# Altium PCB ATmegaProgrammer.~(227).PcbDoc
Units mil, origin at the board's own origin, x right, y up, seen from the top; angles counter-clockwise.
Board outline 2130 x 2245 mil, 2 copper layers (Top Layer, Bottom Layer); 13 components, 10 nets, 72 pads, 3 vias.
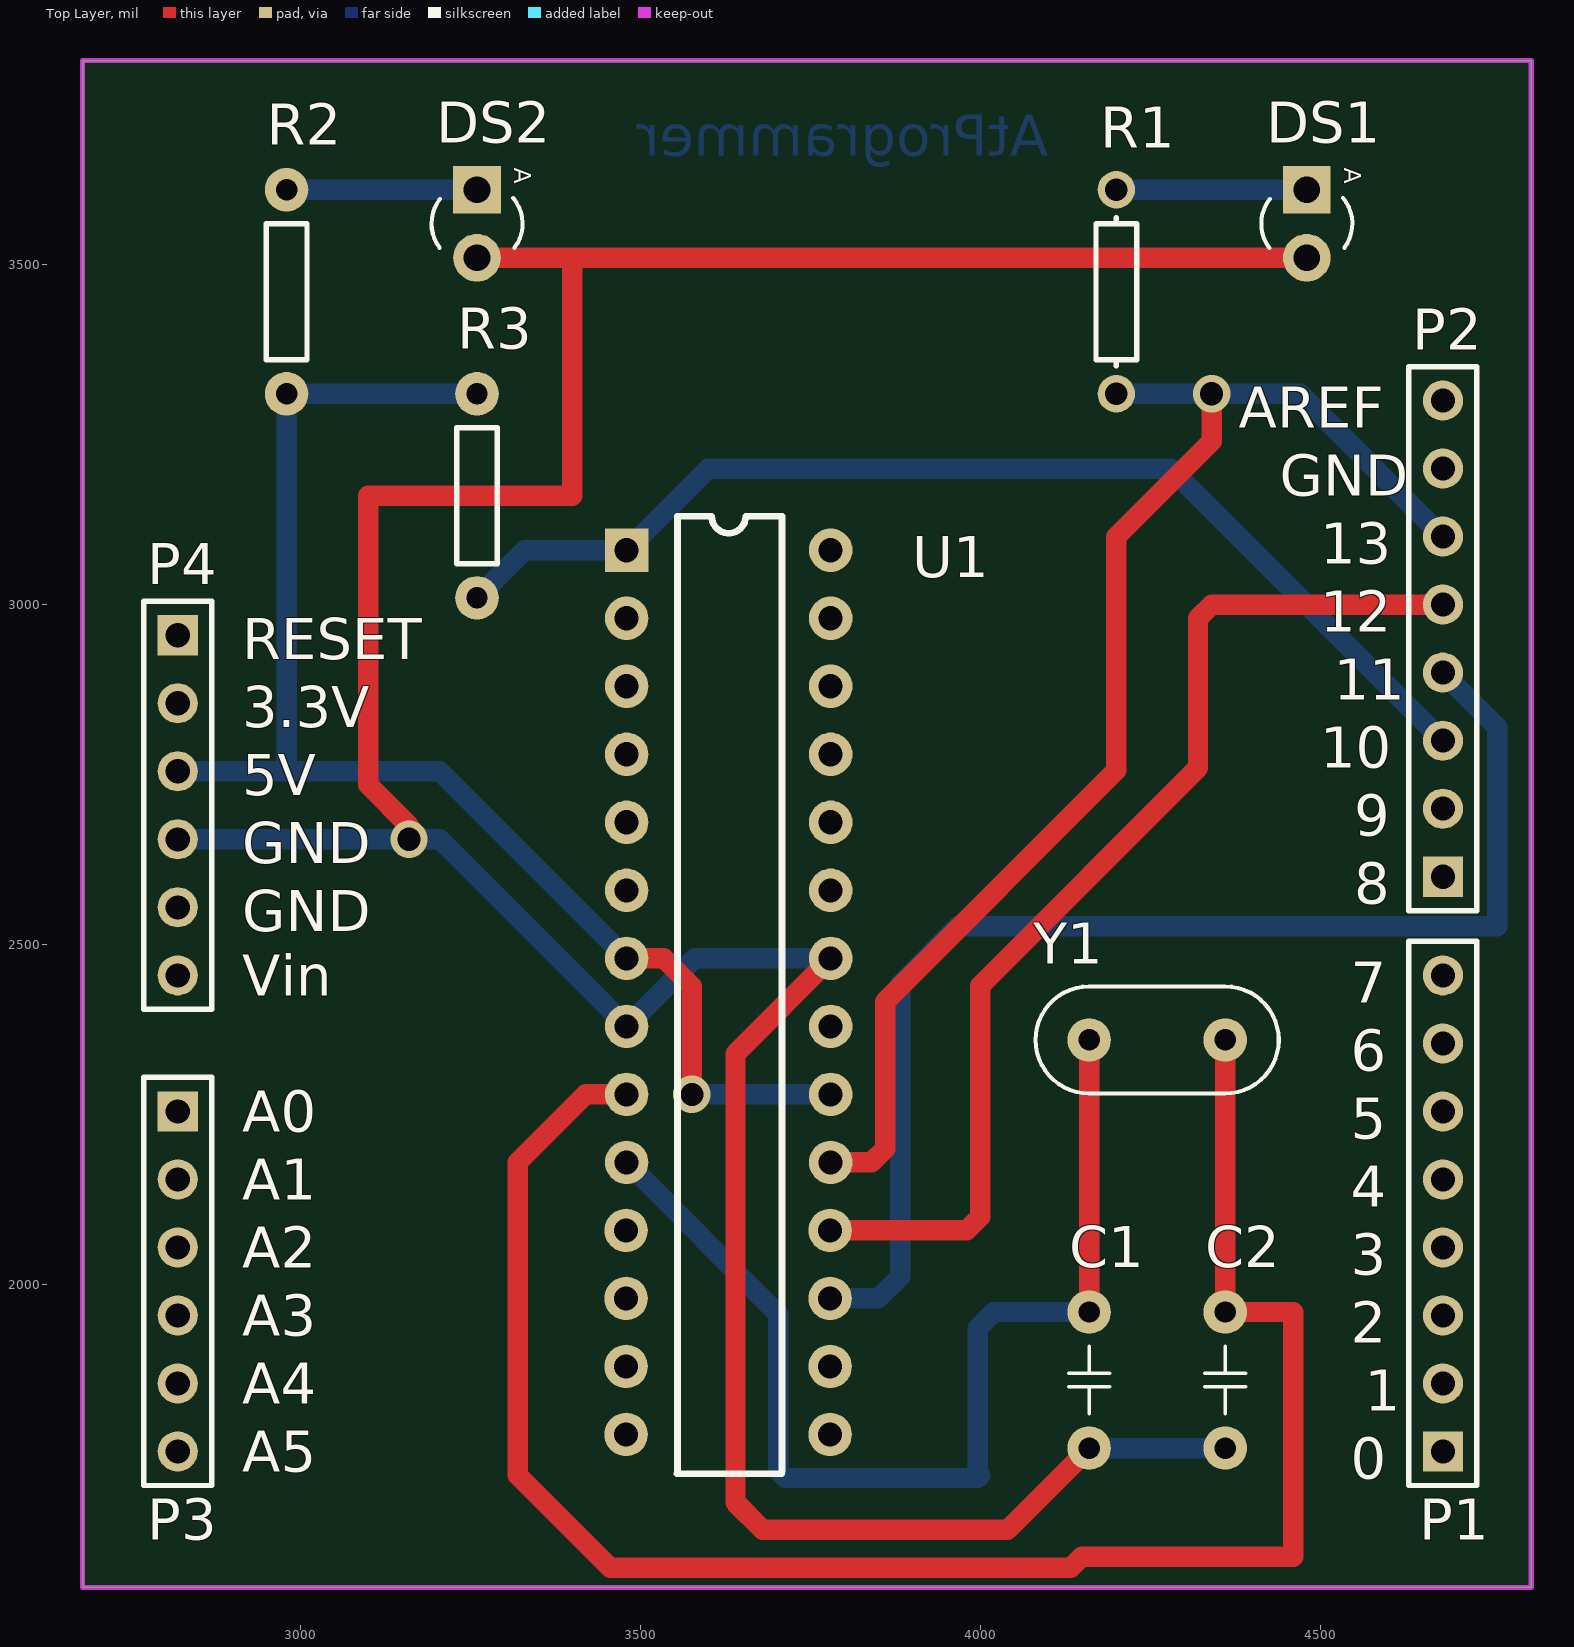
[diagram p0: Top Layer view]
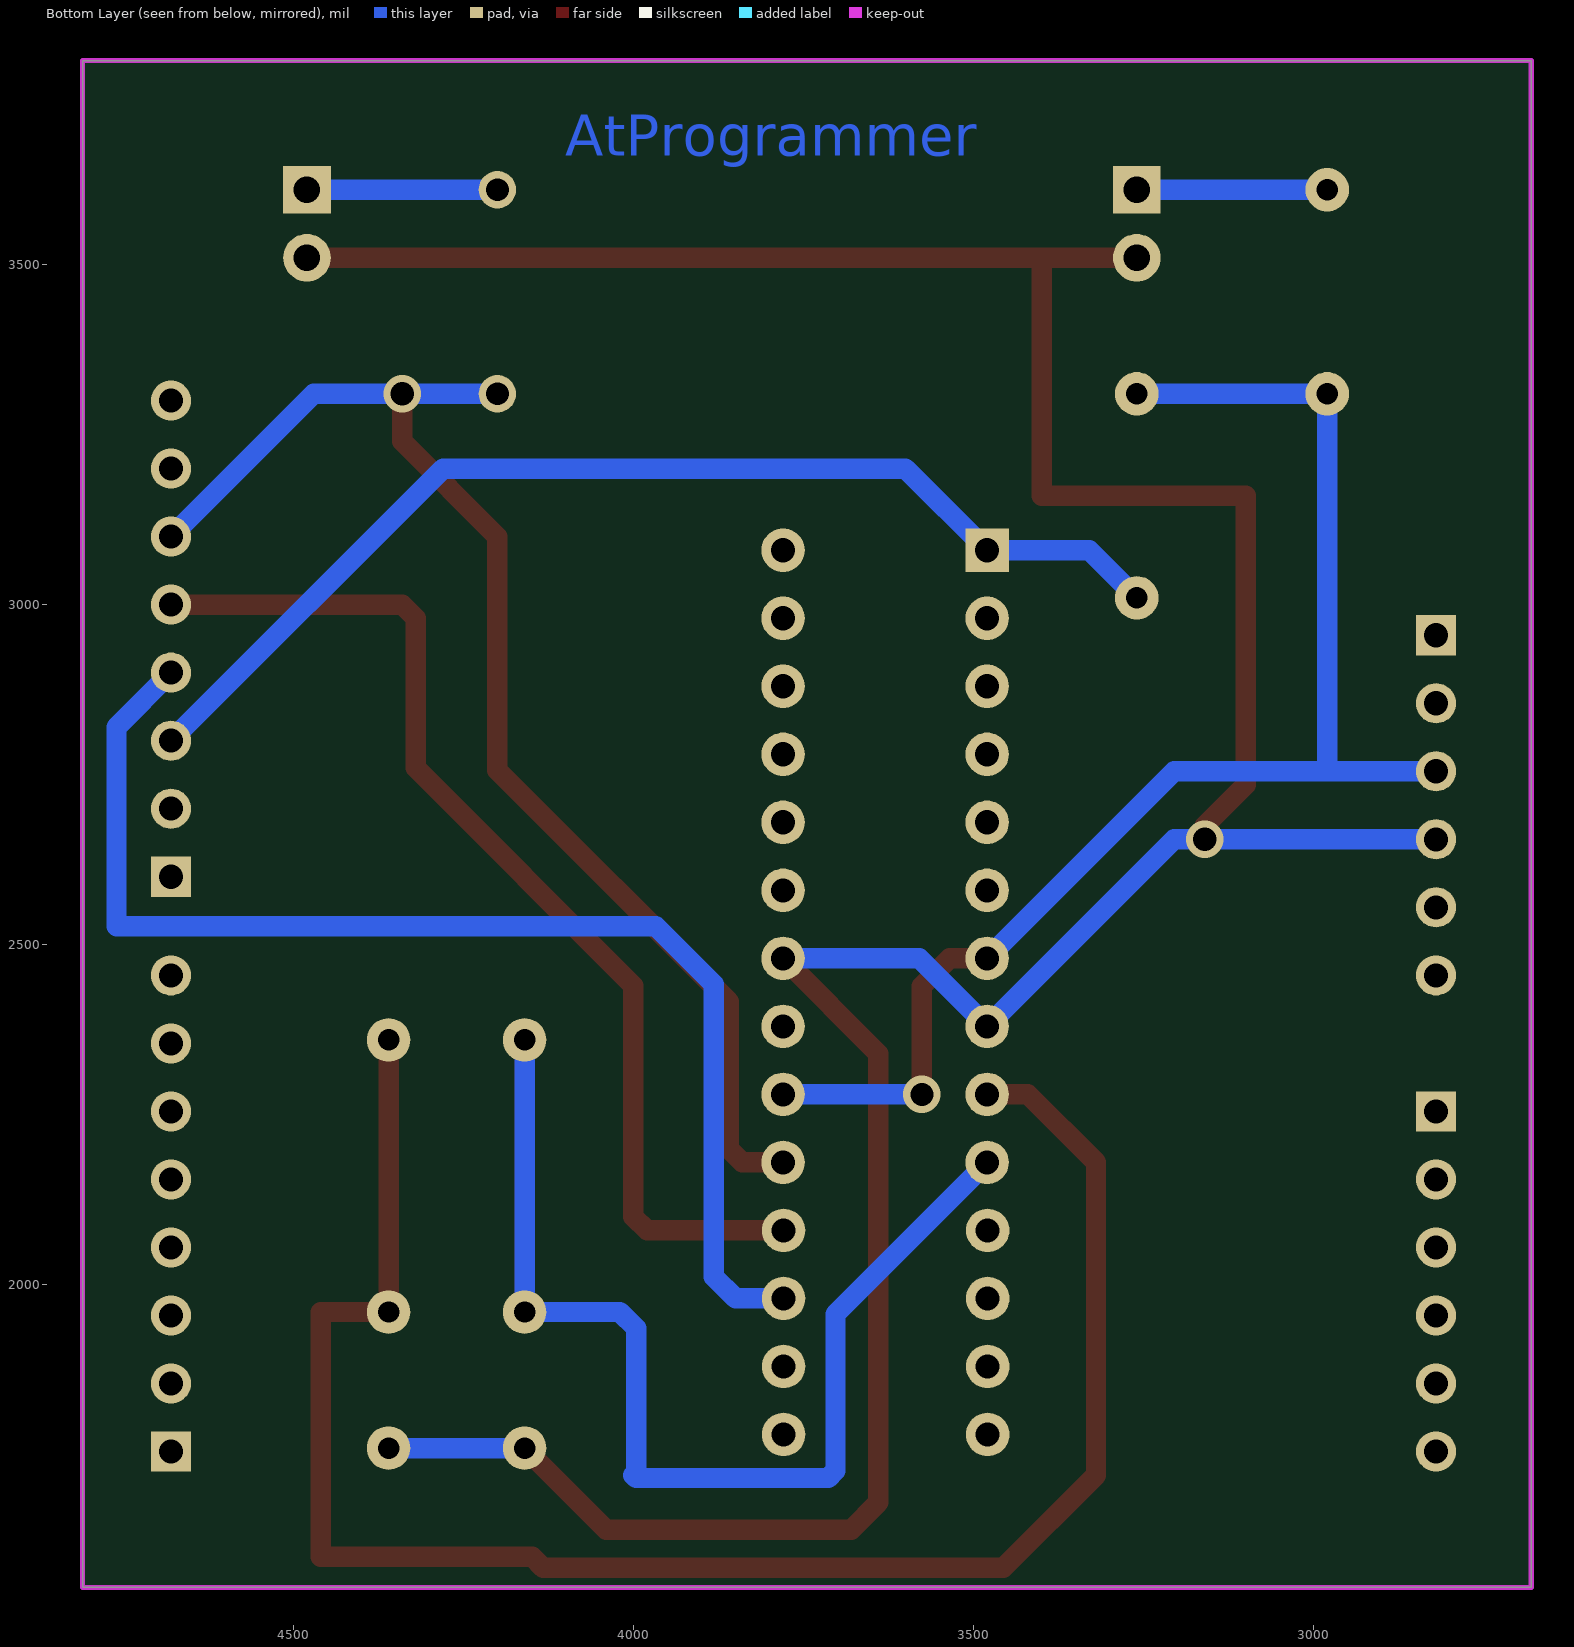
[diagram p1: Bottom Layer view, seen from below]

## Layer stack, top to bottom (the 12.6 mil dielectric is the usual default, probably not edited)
Top Layer: signal copper 1.4
Dielectric: dielectric 12.6, FR-4, Dk 4.8
Bottom Layer: signal copper 1.4

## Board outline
2680,1555 4810,1555 4810,3800 2680,3800

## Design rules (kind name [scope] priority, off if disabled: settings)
Clearance [All] p1: gap=10
PolygonConnect [All] p1: connectstyle=Relief reliefconductorwidth=10 reliefentries=4 polygonreliefangle="90 Angle"
RoutingVias [All] p1: holewidth=28 width=50 viastyle="Through Hole" minholewidth=28 minwidth=50 maxholewidth=28 maxwidth=50
SilkscreenOverComponentPads [All] p1: minsilkscreentomaskgap=10
SolderMaskExpansion [All] p1: expansion=4
Width VCC [All] p1: maxlimit=40 minlimit=20 preferedwidth=30
Width GND [InNet('GND')] p2: maxlimit=40 minlimit=20 preferedwidth=30
Width [All] p3: maxlimit=30 minlimit=10 preferedwidth=20
27 further rules are at their usual default settings.

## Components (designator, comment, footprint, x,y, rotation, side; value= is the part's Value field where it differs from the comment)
C1 "20pF" C200 4160,1860 r180 top
C2 "20pF" C200 4360,1860 r180 top
DS1 "LED" LED-3mm_G 4480,3560 r270 top
DS2 "LED" LED-3mm_G 3260,3560 r270 top
P1 "Header 8" HDR1X8 4680,1755 r90 top
P2 "Header 8" HDR1X8 4680,2600 r90 top
P3 "Header 6" HDR1X6 2820,2255 r270 top
P4 "Header 6" HDR1X6 2820,2955 r270 top
R1 "Res1" AXIAL-0.3#1 4200,3460 r270 top
R2 "220" AXIAL-0.3#2 2980,3460 r270 top
R3 "10k" AXIAL-0.3#2 3260,3160 r90 top
U1 "ATmega328" DIP-28 3480,3080 r270 top
Y1 "16MHz" XTAL4-8 4260,2360 r180 top

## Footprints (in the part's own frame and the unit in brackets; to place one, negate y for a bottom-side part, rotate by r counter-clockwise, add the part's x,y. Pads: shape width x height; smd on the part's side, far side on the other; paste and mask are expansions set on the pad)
AXIAL-0.3#1 [mm] "Axial Device, Thru-Hole; 2 Leads; 0.3 in Pin Spacing"
  round 1.4 hole 0.85: 1(-3.81,0) 2(3.81,0)
  silkscreen extent -2.77,-0.76 2.77,0.76
AXIAL-0.3#2 [mm] "0.3\" Resistor; 2 Leads"
  round 1.626 hole 0.8: 1(-3.81,0) 2(3.81,0)
  silkscreen extent -2.54,-0.76 2.54,0.76, body extent -4.1,-1 4.19,1, height 2.19
C200 [mil] "鹅溅筿甧竟"
  round 64 hole 31.5: 1(0,100) 2(0,-100)
  silkscreen extent -30,-50 30,50, body extent -41,-136 39,135, height 354
DIP-28 [mil]
  rect 64x64 hole 35.43: 1(0,0)
  round 64 hole 35.43: 2(100,0) 3(200,0) 4(300,0) 5(400,0) 6(500,0) 7(600,0) 8(700,0) 9(800,0) 10(900,0) 11(1000,-0.79) 12(1100,-0.79) 13(1200,-0.79) 14(1300,-0.79) 15(1300,299.21) 16(1200,299.21) 17(1100,299.21) 18(1000,299.21) 19(900,300) 20(800,300) 21(700,300) 22(600,300) 23(500,300) 24(400,300) 25(300,300) 26(200,300) 27(100,300) 28(0,300)
  silkscreen extent -50,74 1358,228, body extent -53,-5 1358,304, height 209
HDR1X6 [mm] "Connector; Header; 6 Position"
  rect 1.5x1.5 hole 0.9: 1(0,0)
  round 1.5 hole 0.9: 2(2.54,0) 3(5.08,0) 4(7.62,0) 5(10.16,0) 6(12.7,0)
  silkscreen extent -1.27,-1.27 13.97,1.27
HDR1X8 [mm] "Connector; Header; 8 Position"
  rect 1.5x1.5 hole 0.9: 1(0,0)
  round 1.5 hole 0.9: 2(2.54,0) 3(5.08,0) 4(7.62,0) 5(10.16,0) 6(12.7,0) 7(15.24,0) 8(17.78,0)
  silkscreen extent -1.27,-1.27 19.05,1.27
LED-3mm_G [mil] "3mm LED_Green"
  rect 70x70 hole 39: 1(-50,0)
  round 70 hole 39: 2(50,0)
  silkscreen extent -38,-67 35,67, body extent -66,-68 67,66, height 181
XTAL4-8 [mil]
  round 64 hole 31.5: 1(-100,0) 2(100,0)
  silkscreen extent -179,-79 179,79, body extent -178,-80 192,79, height 157

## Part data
C1 C2: library part Cap, "Capacitor"
DS1 DS2: "Typical INFRARED GaAs LED"
P1 P2: "Header, 8-Pin"
P3 P4: "Header, 6-Pin"
R1: "Resistor"
R2 R3: library part Res, "Resistor"
U1: "Arduino"
Y1: library part XTAL, "Crystal Oscillator"

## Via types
v1: diameter 55, hole 34, Top Layer to Bottom Layer, 3 vias

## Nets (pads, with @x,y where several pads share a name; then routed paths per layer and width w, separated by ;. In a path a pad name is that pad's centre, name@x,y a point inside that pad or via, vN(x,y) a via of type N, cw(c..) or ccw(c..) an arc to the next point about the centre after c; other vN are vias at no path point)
GND: C1.1 C2.1 DS1.2 DS2.2 P4.4 U1.8 U1.22 | length 5139.4
  Top Layer w30: v1@3160,2675 3100,2735 3100,3160 3400,3160 3400,3510 ; DS2.2 3400,3510 ; U1.22 3640,2340 3640,1680 3680,1640 4040,1640 C1.1 ; DS1.2 3400,3510
  Bottom Layer w30: P4.4 v1(3160,2655) 3205,2655 U1.8 3580,2480 U1.22 ; C1.1 C2.1
MISO: P2.5 U1.18 | length 1609.9
  Top Layer w30: U1.18 3980,2080 4000,2100 4000,2440 4320,2760 4320,2980 4340,3000 P2.5
MOSI: P2.4 U1.17 | length 1865.4
  Bottom Layer w30: U1.17 3850,1980 3882,2012 3882,2442 3967,2527 4760,2527 4760,2820 P2.4
NetC1_2: C1.2 U1.10 Y1.2 | length 2042.7
  Top Layer w30: C1.2 Y1.2
  Bottom Layer w30: U1.10 3703,1957 3703,1726.69 3713.69,1716 3996,1716 ; 4000,1720 3996,1716 ; Y1.2 C1.2 4020,1960 3996,1936 3996,1716
NetC2_2: C2.2 U1.9 Y1.1 | length 2724.4
  Top Layer w30: U1.9 3420,2280 3320,2180 3320,1720 3456.06,1583.94 4132.94,1583.94 4149,1600 4460,1600 4460,1960 C2.2 Y1.1
NetDS1_1: DS1.1 R1.1 | length 280
  Bottom Layer w30: R1.1 DS1.1
NetDS2_1: DS2.1 R2.1 | length 280
  Bottom Layer w30: R2.1 DS2.1
RESET: P2.3 R3.1 U1.1 | length 1664.4
  Bottom Layer w30: R3.1 3330,3080 U1.1 3600,3200 4280,3200 P2.3
SCK: P2.6 R1.2 U1.19 | length 1964.1
  Top Layer w30: U1.19 3840,2180 3860,2200 3860,2416.57 4200,2756.57 4200,3100 4340,3240 v1(4340,3310)
  Bottom Layer w30: R1.2 v1(4340,3310) 4470,3310 P2.6
VCC: P4.3 R2.2 R3.2 U1.7 U1.20 | length 2084.8
  Top Layer w30: U1.7 3534.8,2480 3576,2438.8 v1(3576,2280)
  Bottom Layer w30: P4.3 2980,2755 ; R3.2 R2.2 2980,2755 ; U1.7 3205,2755 2980,2755 ; v1(3576,2280) U1.20
pads on no net: P1.1 P1.2 P1.3 P1.4 P1.5 P1.6 P1.7 P1.8 P2.1 P2.2 P2.7 P2.8 P3.1 P3.2 P3.3 P3.4 P3.5 P3.6 P4.1 P4.2 P4.5 P4.6 U1.2 U1.3 U1.4 U1.5 U1.6 U1.11 U1.12 U1.13 U1.14 U1.15 U1.16 U1.21 U1.23 U1.24 U1.25 U1.26 U1.27 U1.28

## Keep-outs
Keep-Out Layer:
  the board outline again, w7.87

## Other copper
Bottom Layer:
  text "AtProgrammer" at 4100,3660 h60

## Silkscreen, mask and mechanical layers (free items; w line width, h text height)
Top Overlay:
  lines w7.87: 0,0 0,200 ; 20,0 35,0 ; 55,0 195,0 ; 2770,2246.75 2770,2255
  text "AREF" at 4380.02,3260 h60
  text "GND" at 4440,3160 h60
  text "13" at 4499.96,3060 h60
  text "12" at 4499.96,2960 h60
  text "RESET" at 2915.05,2920 h60
  text "11" at 4519.95,2860 h60
  text "3.3V" at 2915.05,2820 h60
  text "10" at 4499.96,2760 h60
  text "5V" at 2915.05,2720 h60
  text "9" at 4549.94,2660 h60
  text "GND" at 2915.05,2620 h60
  text "8" at 4549.94,2560 h60
  text "GND" at 2915.05,2520 h60
  text "Vin" at 2915.05,2425 h60
  text "7" at 4544.94,2415 h60
  text "6" at 4544.94,2315 h60
  text "A0" at 2915.05,2225 h60
  text "5" at 4544.94,2215 h60
  text "A1" at 2915.05,2125 h60
  text "4" at 4544.94,2115 h60
  text "A2" at 2915.05,2025 h60
  text "3" at 4544.94,2015 h60
  text "A3" at 2915.05,1925 h60
  text "2" at 4544.94,1915 h60
  text "A4" at 2915.05,1825 h60
  text "1" at 4564.94,1815 h60
  text "A5" at 2915.05,1725 h60
  text "0" at 4544.94,1715 h60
